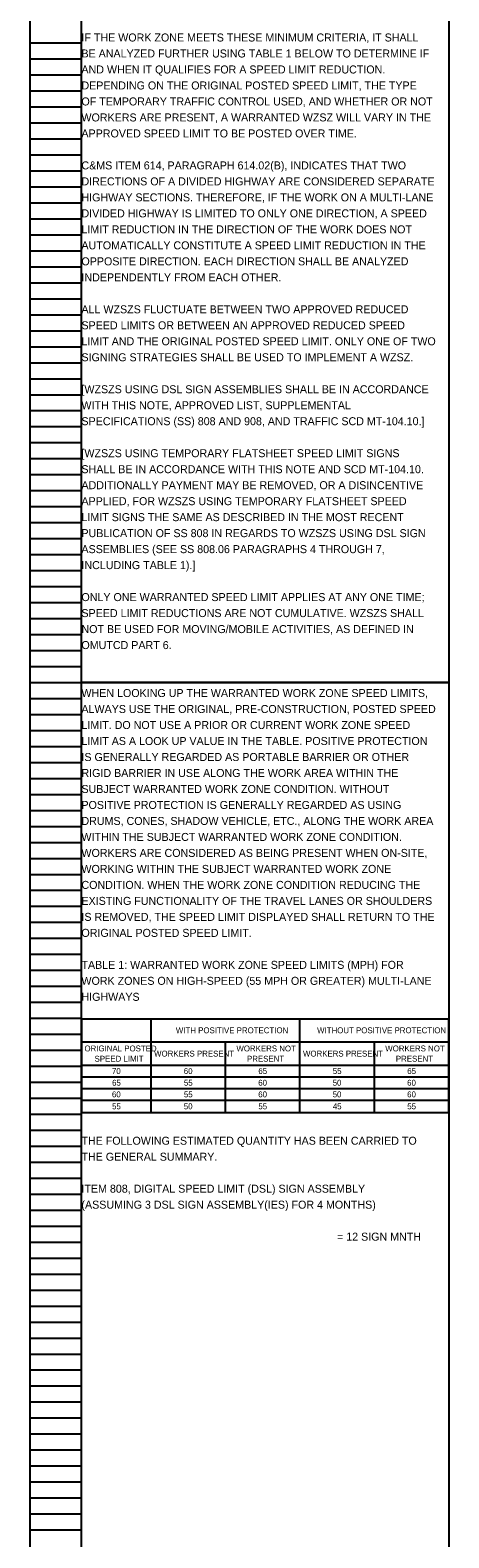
# Model space of a CAD drawing. Extents: x 16463 to 16500, y 5400 to 5823.
# Drawn here: x 16463.05 to 16470.39, y 5506.09 to 5532.5 of the extents above; entities that cross this region are included whole.
import ezdxf

# ---------------------------------------------------------------- set-up
doc = ezdxf.new("R2010")
doc.units = 0
for name, color, linetype in [('Default', 7, 'Continuous'), ('SC_Scratch1', 7, 'Continuous'), ('SH_Data', 7, 'Continuous'), ('SH_Text', 7, 'Continuous')]:
    doc.layers.add(name, color=color, linetype=linetype)

msp = doc.modelspace()

# ---------------------------------------------------------------- linework, layer by layer
at = {"layer": 'Default'}
for p, q in [((16463.949, 5515.184), (16470.382, 5515.184)), ((16463.949, 5515.184), (16463.949, 5513.543)), ((16465.163, 5515.184), (16465.163, 5513.543)), ((16467.772, 5515.184), (16467.772, 5513.543)), ((16470.382, 5515.184), (16470.382, 5513.543)), ((16463.949, 5514.777), (16470.382, 5514.777)), ((16466.467, 5514.777), (16466.467, 5513.543)), ((16469.077, 5514.777), (16469.077, 5513.543)), ((16463.949, 5514.369), (16470.382, 5514.369)), ((16463.949, 5514.165), (16470.382, 5514.165)), ((16463.949, 5513.961), (16470.382, 5513.961)), ((16463.949, 5513.757), (16470.382, 5513.757)), ((16463.949, 5513.543), (16470.382, 5513.543))]:
    msp.add_line(p, q, dxfattribs=at)
at = {"layer": 'SC_Scratch1'}
for points in [[(16463.949, 5541.232), (16470.389, 5541.232), (16470.389, 5521.072), (16463.949, 5521.072)], [(16463.949, 5521.072), (16470.389, 5521.072), (16470.389, 5500.912), (16463.949, 5500.912)]]:
    msp.add_lwpolyline(points, close=True, dxfattribs=at)
at = {"layer": 'SH_Data'}
for p, q in [((16463.049, 5521.072), (16463.049, 5541.232)), ((16463.949, 5521.072), (16463.949, 5541.232)), ((16463.049, 5532.272), (16463.949, 5532.272)), ((16463.049, 5531.992), (16463.949, 5531.992)), ((16463.049, 5531.712), (16463.949, 5531.712)), ((16463.049, 5531.432), (16463.949, 5531.432)), ((16463.049, 5531.152), (16463.949, 5531.152)), ((16463.049, 5530.872), (16463.949, 5530.872)), ((16463.049, 5530.592), (16463.949, 5530.592)), ((16463.049, 5530.312), (16463.949, 5530.312)), ((16463.049, 5530.032), (16463.949, 5530.032)), ((16463.049, 5529.752), (16463.949, 5529.752)), ((16463.049, 5529.472), (16463.949, 5529.472)), ((16463.049, 5529.192), (16463.949, 5529.192)), ((16463.049, 5528.912), (16463.949, 5528.912)), ((16463.049, 5528.632), (16463.949, 5528.632)), ((16463.049, 5528.352), (16463.949, 5528.352)), ((16463.049, 5528.072), (16463.949, 5528.072)), ((16463.049, 5527.792), (16463.949, 5527.792)), ((16463.049, 5527.512), (16463.949, 5527.512)), ((16463.049, 5527.232), (16463.949, 5527.232)), ((16463.049, 5526.952), (16463.949, 5526.952)), ((16463.049, 5526.672), (16463.949, 5526.672)), ((16463.049, 5526.392), (16463.949, 5526.392)), ((16463.049, 5526.112), (16463.949, 5526.112)), ((16463.049, 5525.832), (16463.949, 5525.832)), ((16463.049, 5525.552), (16463.949, 5525.552)), ((16463.049, 5525.272), (16463.949, 5525.272)), ((16463.049, 5524.992), (16463.949, 5524.992)), ((16463.049, 5524.712), (16463.949, 5524.712)), ((16463.049, 5524.432), (16463.949, 5524.432)), ((16463.049, 5524.152), (16463.949, 5524.152)), ((16463.049, 5523.872), (16463.949, 5523.872)), ((16463.049, 5523.592), (16463.949, 5523.592)), ((16463.049, 5523.312), (16463.949, 5523.312)), ((16463.049, 5523.032), (16463.949, 5523.032)), ((16463.049, 5522.752), (16463.949, 5522.752)), ((16463.049, 5522.472), (16463.949, 5522.472)), ((16463.049, 5522.192), (16463.949, 5522.192)), ((16463.049, 5521.912), (16463.949, 5521.912)), ((16463.049, 5521.632), (16463.949, 5521.632)), ((16463.049, 5521.352), (16463.949, 5521.352)), ((16463.049, 5500.912), (16463.049, 5521.072)), ((16463.049, 5521.072), (16463.949, 5521.072)), ((16463.049, 5521.072), (16463.949, 5521.072)), ((16463.949, 5500.912), (16463.949, 5521.072)), ((16463.049, 5520.792), (16463.949, 5520.792)), ((16463.049, 5520.512), (16463.949, 5520.512)), ((16463.049, 5520.232), (16463.949, 5520.232)), ((16463.049, 5519.952), (16463.949, 5519.952)), ((16463.049, 5519.672), (16463.949, 5519.672)), ((16463.049, 5519.392), (16463.949, 5519.392)), ((16463.049, 5519.112), (16463.949, 5519.112)), ((16463.049, 5518.832), (16463.949, 5518.832)), ((16463.049, 5518.552), (16463.949, 5518.552)), ((16463.049, 5518.272), (16463.949, 5518.272)), ((16463.049, 5517.992), (16463.949, 5517.992)), ((16463.049, 5517.712), (16463.949, 5517.712)), ((16463.049, 5517.432), (16463.949, 5517.432)), ((16463.049, 5517.152), (16463.949, 5517.152)), ((16463.049, 5516.872), (16463.949, 5516.872)), ((16463.049, 5516.592), (16463.949, 5516.592)), ((16463.049, 5516.312), (16463.949, 5516.312)), ((16463.049, 5516.032), (16463.949, 5516.032)), ((16463.049, 5515.752), (16463.949, 5515.752)), ((16463.049, 5515.472), (16463.949, 5515.472)), ((16463.049, 5515.192), (16463.949, 5515.192)), ((16463.049, 5514.912), (16463.949, 5514.912)), ((16463.049, 5514.632), (16463.949, 5514.632)), ((16463.049, 5514.352), (16463.949, 5514.352)), ((16463.049, 5514.072), (16463.949, 5514.072)), ((16463.049, 5513.792), (16463.949, 5513.792)), ((16463.049, 5513.512), (16463.949, 5513.512)), ((16463.049, 5513.232), (16463.949, 5513.232)), ((16463.049, 5512.952), (16463.949, 5512.952)), ((16463.049, 5512.672), (16463.949, 5512.672)), ((16463.049, 5512.392), (16463.949, 5512.392)), ((16463.049, 5512.112), (16463.949, 5512.112)), ((16463.049, 5511.832), (16463.949, 5511.832)), ((16463.049, 5511.552), (16463.949, 5511.552)), ((16463.049, 5511.272), (16463.949, 5511.272)), ((16463.049, 5510.992), (16463.949, 5510.992)), ((16463.049, 5510.712), (16463.949, 5510.712)), ((16463.049, 5510.432), (16463.949, 5510.432)), ((16463.049, 5510.152), (16463.949, 5510.152)), ((16463.049, 5509.872), (16463.949, 5509.872)), ((16463.049, 5509.592), (16463.949, 5509.592)), ((16463.049, 5509.312), (16463.949, 5509.312)), ((16463.049, 5509.032), (16463.949, 5509.032)), ((16463.049, 5508.752), (16463.949, 5508.752)), ((16463.049, 5508.472), (16463.949, 5508.472)), ((16463.049, 5508.192), (16463.949, 5508.192)), ((16463.049, 5507.912), (16463.949, 5507.912)), ((16463.049, 5507.632), (16463.949, 5507.632)), ((16463.049, 5507.352), (16463.949, 5507.352)), ((16463.049, 5507.072), (16463.949, 5507.072)), ((16463.049, 5506.792), (16463.949, 5506.792)), ((16463.049, 5506.512), (16463.949, 5506.512)), ((16463.049, 5506.232), (16463.949, 5506.232))]:
    msp.add_line(p, q, dxfattribs=at)

# ---------------------------------------------------------------- texts
at = {"layer": 'Default'}
for s, height, p in [('WITH POSITIVE PROTECTION', 0.10317, (16465.604, 5514.929)), ('WITHOUT POSITIVE PROTECTION', 0.10317, (16468.08, 5514.929)), ('ORIGINAL POSTED ', 0.10317, (16464.002, 5514.611)), ('WORKERS PRESENT', 0.10317, (16465.222, 5514.521)), ('WORKERS NOT ', 0.10317, (16466.665, 5514.611)), ('WORKERS PRESENT', 0.10317, (16467.832, 5514.521)), ('WORKERS NOT ', 0.10317, (16469.274, 5514.611)), ('SPEED LIMIT', 0.10317, (16464.179, 5514.431)), ('70', 0.1032, (16464.484, 5514.215)), ('60', 0.1032, (16465.743, 5514.215)), ('PRESENT', 0.1032, (16466.851, 5514.431)), ('65', 0.1032, (16467.05, 5514.215)), ('55', 0.1032, (16468.355, 5514.215)), ('PRESENT', 0.1032, (16469.46, 5514.431)), ('65', 0.1032, (16469.66, 5514.215)), ('65', 0.1032, (16464.486, 5514.011)), ('55', 0.1032, (16465.745, 5514.011)), ('60', 0.1032, (16467.048, 5514.011)), ('50', 0.1032, (16468.353, 5514.011)), ('60', 0.1032, (16469.658, 5514.011)), ('60', 0.1032, (16464.484, 5513.807)), ('55', 0.1032, (16465.745, 5513.807)), ('60', 0.1032, (16467.048, 5513.807)), ('50', 0.1032, (16468.353, 5513.807)), ('60', 0.1032, (16469.658, 5513.807)), ('55', 0.1032, (16464.486, 5513.598)), ('50', 0.1032, (16465.743, 5513.598)), ('55', 0.1032, (16467.05, 5513.598)), ('45', 0.1032, (16468.355, 5513.598)), ('55', 0.1032, (16469.66, 5513.598))]:
    msp.add_text(s, height=height, dxfattribs=at).set_placement(p)
at = {"layer": 'SH_Text'}
for s, p in [('IF THE WORK ZONE MEETS THESE MINIMUM CRITERIA, IT SHALL ', (16463.949, 5532.297)), ('BE ANALYZED FURTHER USING TABLE 1 BELOW TO DETERMINE IF ', (16463.949, 5532.017)), ('AND WHEN IT QUALIFIES FOR A SPEED LIMIT REDUCTION. ', (16463.949, 5531.737)), ('DEPENDING ON THE ORIGINAL POSTED SPEED LIMIT, THE TYPE ', (16463.949, 5531.457)), ('OF TEMPORARY TRAFFIC CONTROL USED, AND WHETHER OR NOT ', (16463.949, 5531.177)), ('WORKERS ARE PRESENT, A WARRANTED WZSZ WILL VARY IN THE ', (16463.949, 5530.897)), ('APPROVED SPEED LIMIT TO BE POSTED OVER TIME. ', (16463.949, 5530.617)), ('C&MS ITEM 614, PARAGRAPH 614.02(B), INDICATES THAT TWO ', (16463.949, 5530.057)), ('DIRECTIONS OF A DIVIDED HIGHWAY ARE CONSIDERED SEPARATE ', (16463.949, 5529.777)), ('HIGHWAY SECTIONS. THEREFORE, IF THE WORK ON A MULTI-LANE ', (16463.949, 5529.497)), ('DIVIDED HIGHWAY IS LIMITED TO ONLY ONE DIRECTION, A SPEED ', (16463.949, 5529.217)), ('LIMIT REDUCTION IN THE DIRECTION OF THE WORK DOES NOT ', (16463.949, 5528.937)), ('AUTOMATICALLY CONSTITUTE A SPEED LIMIT REDUCTION IN THE ', (16463.949, 5528.657)), ('OPPOSITE DIRECTION. EACH DIRECTION SHALL BE ANALYZED ', (16463.949, 5528.377)), ('INDEPENDENTLY FROM EACH OTHER. ', (16463.949, 5528.097)), ('ALL WZSZS FLUCTUATE BETWEEN TWO APPROVED REDUCED ', (16463.949, 5527.537)), ('SPEED LIMITS OR BETWEEN AN APPROVED REDUCED SPEED ', (16463.949, 5527.257)), ('LIMIT AND THE ORIGINAL POSTED SPEED LIMIT. ONLY ONE OF TWO ', (16463.949, 5526.977)), ('SIGNING STRATEGIES SHALL BE USED TO IMPLEMENT A WZSZ.', (16463.949, 5526.697)), ('[WZSZS USING DSL SIGN ASSEMBLIES SHALL BE IN ACCORDANCE ', (16463.949, 5526.137)), ('WITH THIS NOTE, APPROVED LIST, SUPPLEMENTAL ', (16463.949, 5525.857)), ('SPECIFICATIONS (SS) 808 AND 908, AND TRAFFIC SCD MT-104.10.]', (16463.949, 5525.577)), ('[WZSZS USING TEMPORARY FLATSHEET SPEED LIMIT SIGNS ', (16463.949, 5525.017)), ('SHALL BE IN ACCORDANCE WITH THIS NOTE AND SCD MT-104.10. ', (16463.949, 5524.737)), ('ADDITIONALLY PAYMENT MAY BE REMOVED, OR A DISINCENTIVE ', (16463.949, 5524.457)), ('APPLIED, FOR WZSZS USING TEMPORARY FLATSHEET SPEED ', (16463.949, 5524.177)), ('LIMIT SIGNS THE SAME AS DESCRIBED IN THE MOST RECENT ', (16463.949, 5523.897)), ('PUBLICATION OF SS 808 IN REGARDS TO WZSZS USING DSL SIGN ', (16463.949, 5523.617)), ('ASSEMBLIES (SEE SS 808.06 PARAGRAPHS 4 THROUGH 7, ', (16463.949, 5523.337)), ('INCLUDING TABLE 1).] ', (16463.949, 5523.057)), ('ONLY ONE WARRANTED SPEED LIMIT APPLIES AT ANY ONE TIME; ', (16463.949, 5522.497)), ('SPEED LIMIT REDUCTIONS ARE NOT CUMULATIVE. WZSZS SHALL ', (16463.949, 5522.217)), ('NOT BE USED FOR MOVING/MOBILE ACTIVITIES, AS DEFINED IN ', (16463.949, 5521.937)), ('OMUTCD PART 6.', (16463.949, 5521.657)), ('WHEN LOOKING UP THE WARRANTED WORK ZONE SPEED LIMITS, ', (16463.949, 5520.817)), ('ALWAYS USE THE ORIGINAL, PRE-CONSTRUCTION, POSTED SPEED ', (16463.949, 5520.537)), ('LIMIT. DO NOT USE A PRIOR OR CURRENT WORK ZONE SPEED ', (16463.949, 5520.257)), ('LIMIT AS A LOOK UP VALUE IN THE TABLE. POSITIVE PROTECTION ', (16463.949, 5519.977)), ('IS GENERALLY REGARDED AS PORTABLE BARRIER OR OTHER ', (16463.949, 5519.697)), ('RIGID BARRIER IN USE ALONG THE WORK AREA WITHIN THE ', (16463.949, 5519.417)), ('SUBJECT WARRANTED WORK ZONE CONDITION. WITHOUT ', (16463.949, 5519.137)), ('POSITIVE PROTECTION IS GENERALLY REGARDED AS USING ', (16463.949, 5518.857)), ('DRUMS, CONES, SHADOW VEHICLE, ETC., ALONG THE WORK AREA ', (16463.949, 5518.577)), ('WITHIN THE SUBJECT WARRANTED WORK ZONE CONDITION. ', (16463.949, 5518.297)), ('WORKERS ARE CONSIDERED AS BEING PRESENT WHEN ON-SITE, ', (16463.949, 5518.017)), ('WORKING WITHIN THE SUBJECT WARRANTED WORK ZONE ', (16463.949, 5517.737)), ('CONDITION. WHEN THE WORK ZONE CONDITION REDUCING THE ', (16463.949, 5517.457)), ('EXISTING FUNCTIONALITY OF THE TRAVEL LANES OR SHOULDERS ', (16463.949, 5517.177)), ('IS REMOVED, THE SPEED LIMIT DISPLAYED SHALL RETURN TO THE ', (16463.949, 5516.897)), ('ORIGINAL POSTED SPEED LIMIT. ', (16463.949, 5516.617)), ('TABLE 1: WARRANTED WORK ZONE SPEED LIMITS (MPH) FOR ', (16463.949, 5516.057)), ('WORK ZONES ON HIGH-SPEED (55 MPH OR GREATER) MULTI-LANE ', (16463.949, 5515.777)), ('HIGHWAYS', (16463.949, 5515.497)), ('THE FOLLOWING ESTIMATED QUANTITY HAS BEEN CARRIED TO ', (16463.949, 5512.977)), ('THE GENERAL SUMMARY.', (16463.949, 5512.697)), ('ITEM 808, DIGITAL SPEED LIMIT (DSL) SIGN ASSEMBLY ', (16463.949, 5512.137)), ('(ASSUMING 3 DSL SIGN ASSEMBLY(IES) FOR 4 MONTHS)', (16463.949, 5511.857)), ('= 12 SIGN MNTH', (16468.429, 5511.297))]:
    msp.add_text(s, height=0.14, dxfattribs=at).set_placement(p)

doc.saveas('drawing.dxf')
